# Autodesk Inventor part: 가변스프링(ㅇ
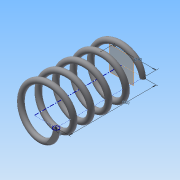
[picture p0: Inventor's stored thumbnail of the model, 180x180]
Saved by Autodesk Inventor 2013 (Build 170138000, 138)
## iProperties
Created: 2018-08
Part Number: 가변스프링(ㅇ
Material: 일반
Document SubType Name: Modeling
Designer: Administrator
Density: 1 g/cm^3
Author: Administrator
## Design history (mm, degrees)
sketch "스케치1"
  geometry: L1 (0, 0)-(20, 0); L2 (20, 0)-(20, 80); L3 (20, 80)-(0, 80); L4 (0, 80)-(0, 0); C1 r 2.5 at (20, 0)
  constraints: 8 end point, 2 parallel, 1 centre point, 1 coincident, 1 horizontal, 1 perpendicular
  dimensions: "d0" = 5 diameter of C1; "d2" = 80 distance between parallel lines of L3 L1 (derived); "d3" = 40 diameter of L2 L4
feature "코일1" pitch "d4" = 10; turns "d6" = 5; dims "d5" = 80 (= d2), "d7" = 0, angle "d8" = 90 deg, angle "d9" = 90 deg, "d10" = 0, "d11" = 0
sketch "스케치2"
  geometry: L1 (-22.5, 0)-(-17.5, 0) reference; 1 further point
  constraints: 1 horizontal alignment
extrude "돌출1" cut sketch "스케치2" stored distance "d12" = 10; taper "d13" = 0 deg
node "작업 평면1"
sketch "스케치3"
  geometry: L1 (22.5, 0)-(17.5, 0) reference; 1 further point
  constraints: 1 horizontal alignment
extrude "돌출2" cut sketch "스케치3" stored distance "d14" = 10; taper "d15" = 0 deg
node "솔리드1"
node "절단 모서리 투영1"
node "절단 모서리 투영2"
